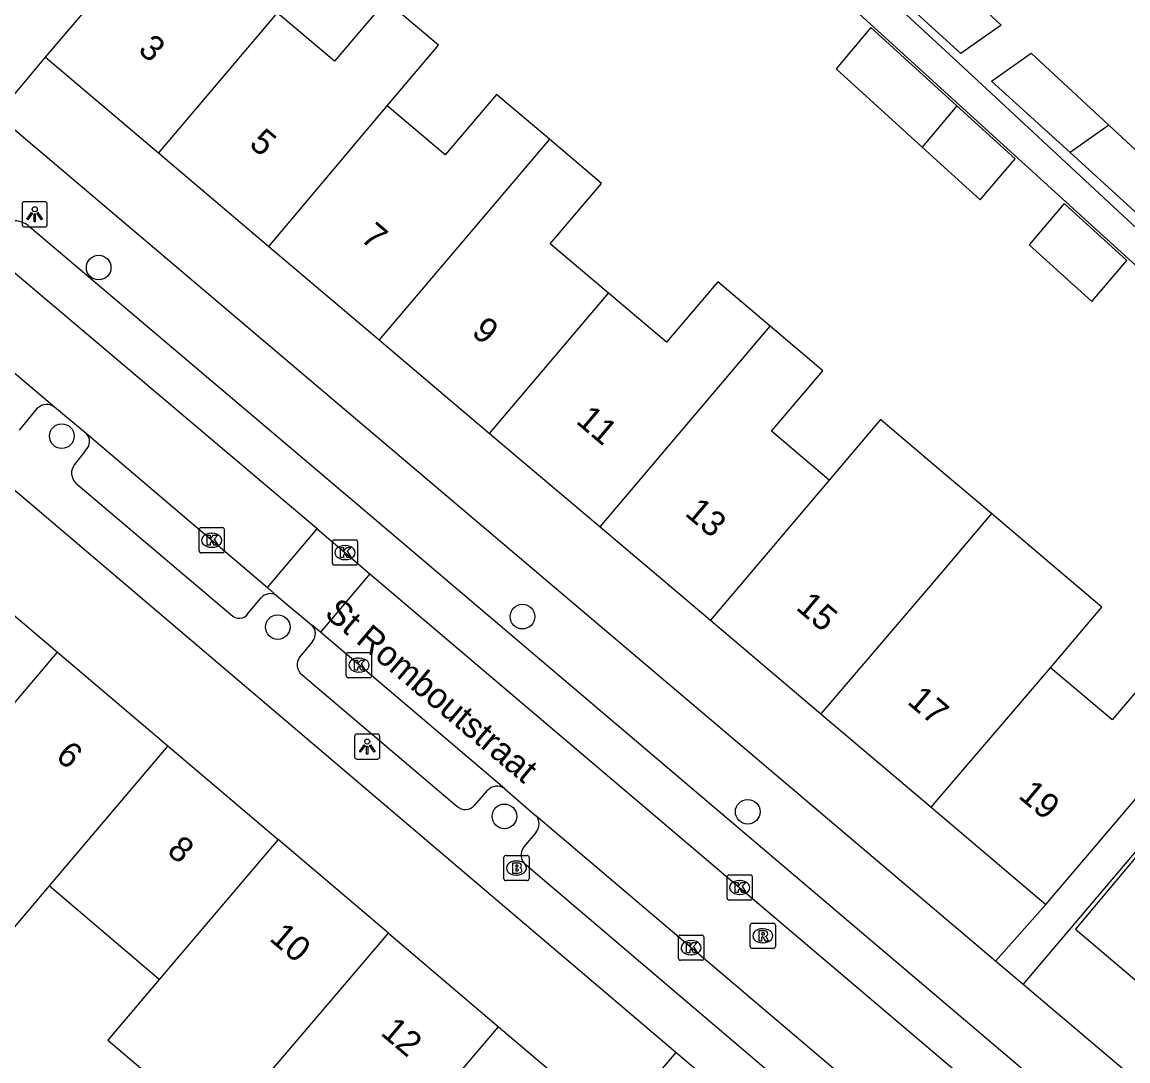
# Model space of a CAD drawing. Extents: x 162532 to 163264, y 381233 to 382042.
# Drawn here: x 162812.29 to 162856.16, y 381629.69 to 381670.92 of the extents above; entities that cross this region are included whole.
import ezdxf

# ---------------------------------------------------------------- set-up
doc = ezdxf.new("R2010")
doc.units = 0
for name, color, linetype in [('IMGEO_Boom', 7, 'Continuous'), ('IMGEO_Brandkraan', 7, 'Continuous'), ('IMGEO_Kolk', 7, 'Continuous'), ('IMGEO_Lichtpunt', 7, 'Continuous'), ('IMGEO_Openbare_ruimte_label', 7, 'Continuous'), ('IMGEO_Pand', 7, 'Continuous'), ('IMGEO_Pand_nummerreeks', 7, 'Continuous'), ('IMGEO_Rijbaan_lokaal_open', 7, 'Continuous'), ('IMGEO_Rioolput', 7, 'Continuous'), ('IMGEO_Voetpad_open', 7, 'Continuous')]:
    doc.layers.add(name, color=color, linetype=linetype)

msp = doc.modelspace()

# ---------------------------------------------------------------- linework, layer by layer
at = {"layer": 'IMGEO_Boom'}
for centre in [(162815.332, 381661.173), (162813.869, 381654.484), (162832.145, 381647.32), (162822.437, 381646.905), (162831.429, 381639.392), (162841.082, 381639.575)]:
    msp.add_circle(centre, 0.489, dxfattribs=at)
at = {"layer": 'IMGEO_Brandkraan'}
for p, q in [((162831.406, 381636.915), (162831.406, 381637.767)), ((162831.481, 381637.841), (162832.333, 381637.841)), ((162831.894, 381637.621), (162831.919, 381637.621)), ((162832.407, 381637.767), (162832.407, 381636.915)), ((162832.333, 381636.841), (162831.481, 381636.841)), ((162831.917, 381637.061), (162831.892, 381637.061))]:
    msp.add_line(p, q, dxfattribs=at)
for points in [[(162831.406, 381636.915), (162831.406, 381637.767)], [(162831.481, 381637.841), (162832.333, 381637.841)], [(162832.407, 381637.767), (162832.407, 381636.915)], [(162831.754, 381637.541), (162831.754, 381637.141), (162831.967, 381637.141)], [(162831.985, 381637.541), (162831.754, 381637.541)], [(162831.933, 381637.46), (162831.879, 381637.46), (162831.879, 381637.384)], [(162831.879, 381637.384), (162831.932, 381637.384)], [(162831.941, 381637.308), (162831.879, 381637.308), (162831.879, 381637.227)], [(162831.879, 381637.227), (162831.941, 381637.227)], [(162832.333, 381636.841), (162831.481, 381636.841)]]:
    msp.add_lwpolyline(points, dxfattribs=at)
for centre, radius, start, end in [((162831.483, 381637.765), 0.0765, 91.552, 178.448), ((162831.483, 381637.765), 0.0765, 91.552, 178.448), ((162832.331, 381637.765), 0.0765, 1.552, 88.448), ((162832.331, 381637.765), 0.0765, 1.552, 88.448), ((162831.934, 381637.422), 0.0379, 267.8285, 90.9355), ((162831.942, 381637.267), 0.0404, 269.8759, 90.5077), ((162831.989, 381637.396), 0.145, 59.4692, 91.5367), ((162832.014, 381637.443), 0.0922, 285.5137, 58.1501), ((162832.019, 381637.251), 0.105, 301.3115, 78.989), ((162831.483, 381636.917), 0.0765, 181.552, 268.448), ((162831.483, 381636.917), 0.0765, 181.552, 268.448), ((162831.973, 381637.392), 0.251, 268.6676, 293.5347), ((162832.331, 381636.917), 0.0765, 271.552, 358.448), ((162832.331, 381636.917), 0.0765, 271.552, 358.448)]:
    msp.add_arc(centre, radius, start, end, dxfattribs=at)
for centre, major_axis, ratio, start_param, end_param in [((162831.893, 381637.341), (-0.387, 0.002), 0.722429, 4.712389, 7.853982), ((162831.918, 381637.341), (-0.39, 0.002), 0.717154, 1.570796, 4.712389)]:
    msp.add_ellipse(centre, major_axis=major_axis, ratio=ratio, start_param=start_param, end_param=end_param, dxfattribs=at)
at = {"layer": 'IMGEO_Kolk'}
for p, q in [((162819.316, 381649.925), (162819.316, 381650.777)), ((162819.391, 381650.851), (162820.243, 381650.851)), ((162820.317, 381650.777), (162820.317, 381649.925)), ((162819.804, 381650.631), (162819.829, 381650.631)), ((162824.68, 381650.363), (162825.532, 381650.363)), ((162819.827, 381650.071), (162819.802, 381650.071)), ((162824.605, 381649.437), (162824.605, 381650.289)), ((162825.093, 381650.143), (162825.118, 381650.143)), ((162825.606, 381650.289), (162825.606, 381649.437)), ((162820.243, 381649.851), (162819.391, 381649.851)), ((162825.116, 381649.583), (162825.091, 381649.583)), ((162825.532, 381649.363), (162824.68, 381649.363)), ((162825.157, 381644.969), (162825.157, 381645.821)), ((162825.232, 381645.895), (162826.084, 381645.895)), ((162825.645, 381645.675), (162825.67, 381645.675)), ((162826.158, 381645.821), (162826.158, 381644.969)), ((162825.668, 381645.115), (162825.643, 381645.115)), ((162826.084, 381644.895), (162825.232, 381644.895)), ((162840.263, 381636.143), (162840.263, 381636.995)), ((162840.338, 381637.069), (162841.19, 381637.069)), ((162840.751, 381636.849), (162840.776, 381636.849)), ((162841.264, 381636.995), (162841.264, 381636.143)), ((162841.19, 381636.069), (162840.338, 381636.069)), ((162840.774, 381636.289), (162840.749, 381636.289)), ((162838.335, 381633.755), (162838.335, 381634.607)), ((162838.41, 381634.681), (162839.262, 381634.681)), ((162839.336, 381634.607), (162839.336, 381633.755)), ((162838.823, 381634.461), (162838.848, 381634.461)), ((162839.262, 381633.681), (162838.41, 381633.681)), ((162838.846, 381633.901), (162838.821, 381633.901))]:
    msp.add_line(p, q, dxfattribs=at)
for points in [[(162819.316, 381649.925), (162819.316, 381650.777)], [(162819.391, 381650.851), (162820.243, 381650.851)], [(162820.317, 381650.777), (162820.317, 381649.925)], [(162819.637, 381650.551), (162819.76, 381650.551), (162819.76, 381650.4), (162819.89, 381650.551), (162820.054, 381650.551), (162819.908, 381650.4), (162820.061, 381650.151), (162819.909, 381650.151), (162819.824, 381650.315), (162819.76, 381650.248), (162819.76, 381650.151), (162819.637, 381650.151), (162819.637, 381650.551)], [(162824.68, 381650.363), (162825.532, 381650.363)], [(162824.605, 381649.437), (162824.605, 381650.289)], [(162824.926, 381650.063), (162825.049, 381650.063), (162825.049, 381649.912), (162825.179, 381650.063), (162825.343, 381650.063), (162825.197, 381649.912), (162825.35, 381649.663), (162825.198, 381649.663), (162825.113, 381649.827), (162825.049, 381649.76), (162825.049, 381649.663), (162824.926, 381649.663), (162824.926, 381650.063)], [(162825.606, 381650.289), (162825.606, 381649.437)], [(162820.243, 381649.851), (162819.391, 381649.851)], [(162825.532, 381649.363), (162824.68, 381649.363)], [(162825.157, 381644.969), (162825.157, 381645.821)], [(162825.232, 381645.895), (162826.084, 381645.895)], [(162825.478, 381645.595), (162825.601, 381645.595), (162825.601, 381645.444), (162825.731, 381645.595), (162825.895, 381645.595), (162825.749, 381645.444), (162825.902, 381645.195), (162825.75, 381645.195), (162825.665, 381645.359), (162825.601, 381645.292), (162825.601, 381645.195), (162825.478, 381645.195), (162825.478, 381645.595)], [(162826.158, 381645.821), (162826.158, 381644.969)], [(162826.084, 381644.895), (162825.232, 381644.895)], [(162840.263, 381636.143), (162840.263, 381636.995)], [(162840.338, 381637.069), (162841.19, 381637.069)], [(162840.584, 381636.769), (162840.707, 381636.769), (162840.707, 381636.618), (162840.837, 381636.769), (162841.001, 381636.769), (162840.855, 381636.618), (162841.008, 381636.369), (162840.856, 381636.369), (162840.771, 381636.533), (162840.707, 381636.466), (162840.707, 381636.369), (162840.584, 381636.369), (162840.584, 381636.769)], [(162841.264, 381636.995), (162841.264, 381636.143)], [(162841.19, 381636.069), (162840.338, 381636.069)], [(162838.335, 381633.755), (162838.335, 381634.607)], [(162838.41, 381634.681), (162839.262, 381634.681)], [(162839.336, 381634.607), (162839.336, 381633.755)], [(162838.656, 381634.381), (162838.779, 381634.381), (162838.779, 381634.23), (162838.909, 381634.381), (162839.073, 381634.381), (162838.927, 381634.23), (162839.08, 381633.981), (162838.928, 381633.981), (162838.843, 381634.145), (162838.779, 381634.078), (162838.779, 381633.981), (162838.656, 381633.981), (162838.656, 381634.381)], [(162839.262, 381633.681), (162838.41, 381633.681)]]:
    msp.add_lwpolyline(points, dxfattribs=at)
for centre, start, end in [((162819.393, 381650.775), 91.552, 178.448), ((162819.393, 381650.775), 91.552, 178.448), ((162820.241, 381650.775), 1.552, 88.448), ((162820.241, 381650.775), 1.552, 88.448), ((162824.682, 381650.287), 91.552, 178.448), ((162824.682, 381650.287), 91.552, 178.448), ((162825.53, 381650.287), 1.552, 88.448), ((162825.53, 381650.287), 1.552, 88.448), ((162819.393, 381649.927), 181.552, 268.448), ((162819.393, 381649.927), 181.552, 268.448), ((162820.241, 381649.927), 271.552, 358.448), ((162820.241, 381649.927), 271.552, 358.448), ((162824.682, 381649.439), 181.552, 268.448), ((162824.682, 381649.439), 181.552, 268.448), ((162825.53, 381649.439), 271.552, 358.448), ((162825.53, 381649.439), 271.552, 358.448), ((162825.234, 381645.819), 91.552, 178.448), ((162825.234, 381645.819), 91.552, 178.448), ((162826.082, 381645.819), 1.552, 88.448), ((162826.082, 381645.819), 1.552, 88.448), ((162825.234, 381644.971), 181.552, 268.448), ((162825.234, 381644.971), 181.552, 268.448), ((162826.082, 381644.971), 271.552, 358.448), ((162826.082, 381644.971), 271.552, 358.448), ((162840.34, 381636.993), 91.552, 178.448), ((162840.34, 381636.993), 91.552, 178.448), ((162841.188, 381636.993), 1.552, 88.448), ((162841.188, 381636.993), 1.552, 88.448), ((162840.34, 381636.145), 181.552, 268.448), ((162840.34, 381636.145), 181.552, 268.448), ((162841.188, 381636.145), 271.552, 358.448), ((162841.188, 381636.145), 271.552, 358.448), ((162838.412, 381634.605), 91.552, 178.448), ((162838.412, 381634.605), 91.552, 178.448), ((162839.26, 381634.605), 1.552, 88.448), ((162839.26, 381634.605), 1.552, 88.448), ((162838.412, 381633.757), 181.552, 268.448), ((162838.412, 381633.757), 181.552, 268.448), ((162839.26, 381633.757), 271.552, 358.448), ((162839.26, 381633.757), 271.552, 358.448)]:
    msp.add_arc(centre, 0.0765, start, end, dxfattribs=at)
for centre, major_axis, ratio, start_param, end_param in [((162819.803, 381650.351), (-0.387, 0.002), 0.722429, 4.712389, 7.853982), ((162819.828, 381650.351), (-0.39, 0.002), 0.717154, 1.570796, 4.712389), ((162825.092, 381649.863), (-0.387, 0.002), 0.722429, 4.712389, 7.853982), ((162825.117, 381649.863), (-0.39, 0.002), 0.717154, 1.570796, 4.712389), ((162825.644, 381645.395), (-0.387, 0.002), 0.722429, 4.712389, 7.853982), ((162825.669, 381645.395), (-0.39, 0.002), 0.717154, 1.570796, 4.712389), ((162840.75, 381636.569), (-0.387, 0.002), 0.722429, 4.712389, 7.853982), ((162840.775, 381636.569), (-0.39, 0.002), 0.717154, 1.570796, 4.712389), ((162838.822, 381634.181), (-0.387, 0.002), 0.722429, 4.712389, 7.853982), ((162838.847, 381634.181), (-0.39, 0.002), 0.717154, 1.570796, 4.712389)]:
    msp.add_ellipse(centre, major_axis=major_axis, ratio=ratio, start_param=start_param, end_param=end_param, dxfattribs=at)
at = {"layer": 'IMGEO_Lichtpunt'}
for p, q in [((162812.295, 381663.69), (162812.295, 381662.883)), ((162812.295, 381663.69), (162812.295, 381662.883)), ((162813.197, 381663.785), (162812.389, 381663.785)), ((162813.197, 381663.785), (162812.389, 381663.785)), ((162813.291, 381662.883), (162813.291, 381663.69)), ((162813.291, 381662.883), (162813.291, 381663.69)), ((162812.389, 381662.789), (162813.197, 381662.789)), ((162812.389, 381662.789), (162813.197, 381662.789)), ((162825.487, 381642.565), (162825.487, 381641.758)), ((162825.487, 381642.565), (162825.487, 381641.758)), ((162826.389, 381642.66), (162825.581, 381642.66)), ((162826.389, 381642.66), (162825.581, 381642.66)), ((162826.483, 381641.758), (162826.483, 381642.565)), ((162826.483, 381641.758), (162826.483, 381642.565)), ((162825.581, 381641.664), (162826.389, 381641.664)), ((162825.581, 381641.664), (162826.389, 381641.664))]:
    msp.add_line(p, q, dxfattribs=at)
for points in [[(162812.669, 381663.354), (162812.708, 381663.326), (162812.52, 381663.064), (162812.482, 381663.091), (162812.669, 381663.354)], [(162812.771, 381663.306), (162812.818, 381663.306), (162812.818, 381662.984), (162812.771, 381662.984), (162812.771, 381663.306)], [(162812.881, 381663.326), (162812.919, 381663.353), (162813.106, 381663.091), (162813.067, 381663.063), (162812.881, 381663.326)], [(162825.861, 381642.229), (162825.9, 381642.201), (162825.712, 381641.939), (162825.674, 381641.966), (162825.861, 381642.229)], [(162825.963, 381642.181), (162826.01, 381642.181), (162826.01, 381641.859), (162825.963, 381641.859), (162825.963, 381642.181)], [(162826.073, 381642.201), (162826.111, 381642.228), (162826.298, 381641.966), (162826.259, 381641.938), (162826.073, 381642.201)]]:
    msp.add_lwpolyline(points, dxfattribs=at)
for centre in [(162812.794, 381663.488), (162825.986, 381642.363)]:
    msp.add_circle(centre, 0.0994, dxfattribs=at)
for centre, start, end in [((162812.389, 381663.69), 90, 180), ((162812.389, 381663.69), 90, 180), ((162813.197, 381663.69), 0, 90), ((162813.197, 381663.69), 0, 90), ((162812.389, 381662.883), 180, 270), ((162812.389, 381662.883), 180, 270), ((162813.197, 381662.883), 270, 0), ((162813.197, 381662.883), 270, 360), ((162825.581, 381642.565), 90, 180), ((162825.581, 381642.565), 90, 180), ((162826.389, 381642.565), 0, 90), ((162826.389, 381642.565), 0, 90), ((162825.581, 381641.758), 180, 270), ((162825.581, 381641.758), 180, 270), ((162826.389, 381641.758), 270, 0), ((162826.389, 381641.758), 270, 360)]:
    msp.add_arc(centre, 0.0946, start, end, dxfattribs=at)
at = {"layer": 'IMGEO_Pand'}
for points in [[(162846.86, 381674.769), (162851.137, 381670.798), (162849.541, 381669.672), (162845.216, 381673.608)], [(162813.228, 381669.519), (162815.562, 381672.274)], [(162826.776, 381667.595), (162828.812, 381669.998), (162826.729, 381671.763), (162824.693, 381669.36), (162822.416, 381671.289)], [(162822.416, 381671.289), (162817.704, 381665.727)], [(162849.383, 381667.591), (162845.97, 381670.698), (162844.584, 381669.062), (162847.997, 381665.955)], [(162853.868, 381665.734), (162850.749, 381668.572), (162852.331, 381669.689), (162855.414, 381666.826)], [(162813.228, 381669.519), (162817.704, 381665.727)], [(162833.211, 381666.271), (162831.117, 381668.045), (162829.081, 381665.642), (162826.776, 381667.595)], [(162822.083, 381662.016), (162826.776, 381667.595)], [(162849.383, 381667.591), (162847.997, 381665.955)], [(162847.997, 381665.955), (162850.303, 381663.856), (162851.689, 381665.492), (162849.383, 381667.591)], [(162855.414, 381666.826), (162859.622, 381662.919), (162858.404, 381661.606), (162853.868, 381665.734)], [(162855.414, 381666.826), (162853.868, 381665.734)], [(162833.211, 381666.271), (162826.462, 381658.305)], [(162835.554, 381660.157), (162833.247, 381662.112), (162835.283, 381664.515), (162833.211, 381666.271)], [(162817.704, 381665.727), (162822.083, 381662.016)], [(162856.122, 381661.459), (162853.639, 381663.718), (162852.253, 381662.082), (162854.735, 381659.823), (162856.122, 381661.459)], [(162822.083, 381662.016), (162826.462, 381658.305)], [(162841.97, 381658.849), (162839.892, 381660.61), (162837.855, 381658.207), (162835.554, 381660.157)], [(162830.842, 381654.594), (162835.554, 381660.157)], [(162835.221, 381650.884), (162841.97, 381658.849)], [(162844.313, 381652.735), (162842.021, 381654.677), (162844.057, 381657.08), (162841.97, 381658.849)], [(162826.462, 381658.305), (162830.842, 381654.594)], [(162850.749, 381651.41), (162848.666, 381653.175), (162846.349, 381655.138), (162844.313, 381652.735)], [(162830.842, 381654.594), (162835.221, 381650.884)], [(162844.313, 381652.735), (162839.6, 381647.173)], [(162850.749, 381651.41), (162848.713, 381649.007), (162843.98, 381643.462)], [(162853.1, 381645.29), (162855.136, 381647.693), (162853.053, 381649.458), (162850.749, 381651.41)], [(162835.221, 381650.884), (162839.6, 381647.173)], [(162809.322, 381649.618), (162813.697, 381645.903)], [(162839.6, 381647.173), (162843.98, 381643.462)], [(162808.987, 381640.357), (162813.697, 381645.903)], [(162813.697, 381645.903), (162818.073, 381642.188)], [(162859.663, 381643.857), (162857.58, 381645.622), (162855.544, 381643.219), (162853.1, 381645.29)], [(162848.359, 381639.752), (162853.1, 381645.29)], [(162852.914, 381635.892), (162856.147, 381639.707), (162857.627, 381641.454), (162859.663, 381643.857)], [(162843.98, 381643.462), (162848.359, 381639.752)], [(162863.237, 381636.7), (162860.84, 381638.731), (162862.87, 381641.156), (162860.788, 381642.922), (162858.757, 381640.496), (162857.296, 381638.751), (162854.086, 381634.917), (162858.532, 381631.147)], [(162818.073, 381642.188), (162813.366, 381636.633)], [(162818.073, 381642.188), (162822.448, 381638.473)], [(162813.366, 381636.633), (162811.32, 381634.226), (162809.238, 381635.993), (162811.286, 381638.402), (162808.987, 381640.357)], [(162848.359, 381639.752), (162852.914, 381635.892)], [(162822.448, 381638.473), (162817.732, 381632.92)], [(162826.824, 381634.758), (162822.448, 381638.473)], [(162817.732, 381632.92), (162813.366, 381636.633)], [(162820.066, 381626.801), (162826.824, 381634.758)], [(162826.824, 381634.758), (162831.199, 381631.044)], [(162817.732, 381632.92), (162815.691, 381630.516), (162818.218, 381628.37), (162820.066, 381626.801)], [(162826.477, 381625.484), (162831.199, 381631.044)], [(162831.199, 381631.044), (162835.786, 381627.149)]]:
    msp.add_lwpolyline(points, dxfattribs=at)
at = {"layer": 'IMGEO_Rijbaan_lokaal_open'}
for points in [[(162823.995, 381650.801), (162811.413, 381661.436), (162809.303, 381663.293)], [(162805.425, 381662.797), (162807.552, 381660.807), (162809.65, 381658.966), (162813.578, 381655.64)], [(162813.578, 381655.64), (162814.832, 381654.599)], [(162814.832, 381654.599), (162822.027, 381648.47)], [(162822.027, 381648.47), (162823.995, 381650.801)], [(162823.995, 381650.801), (162825.09, 381649.875), (162826.092, 381649.024)], [(162826.092, 381649.024), (162824.128, 381646.697)], [(162826.092, 381649.024), (162869.033, 381612.565)], [(162822.404, 381648.149), (162822.027, 381648.47)], [(162822.404, 381648.149), (162823.781, 381646.991)], [(162824.128, 381646.697), (162823.781, 381646.991)], [(162831.43, 381640.494), (162824.128, 381646.697)], [(162831.43, 381640.494), (162832.662, 381639.429)], [(162850.293, 381624.446), (162832.662, 381639.429)]]:
    msp.add_lwpolyline(points, dxfattribs=at)
at = {"layer": 'IMGEO_Rioolput'}
for p, q in [((162841.179, 381634.226), (162841.179, 381635.078)), ((162841.254, 381635.152), (162842.106, 381635.152)), ((162842.18, 381635.078), (162842.18, 381634.226)), ((162841.667, 381634.932), (162841.692, 381634.932)), ((162842.106, 381634.152), (162841.254, 381634.152)), ((162841.69, 381634.372), (162841.665, 381634.372))]:
    msp.add_line(p, q, dxfattribs=at)
for points in [[(162841.179, 381634.226), (162841.179, 381635.078)], [(162841.254, 381635.152), (162842.106, 381635.152)], [(162842.18, 381635.078), (162842.18, 381634.226)], [(162841.768, 381634.85), (162841.516, 381634.852), (162841.516, 381634.452)], [(162841.516, 381634.452), (162841.64, 381634.452), (162841.64, 381634.614), (162841.651, 381634.614)], [(162841.694, 381634.771), (162841.64, 381634.771), (162841.64, 381634.69)], [(162841.64, 381634.69), (162841.692, 381634.69)], [(162841.698, 381634.585), (162841.769, 381634.452), (162841.909, 381634.452), (162841.844, 381634.578)], [(162842.106, 381634.152), (162841.254, 381634.152)]]:
    msp.add_lwpolyline(points, dxfattribs=at)
for centre, radius, start, end in [((162841.256, 381635.076), 0.0765, 91.552, 178.448), ((162841.256, 381635.076), 0.0765, 91.552, 178.448), ((162842.104, 381635.076), 0.0765, 1.552, 88.448), ((162842.104, 381635.076), 0.0765, 1.552, 88.448), ((162841.65, 381634.561), 0.0533, 26.0293, 88.6989), ((162841.676, 381634.879), 0.19, 274.7715, 282.9687), ((162841.7, 381634.675), 0.0964, 77.0061, 93.1865), ((162841.714, 381634.732), 0.0378, 276.6634, 79.6772), ((162841.767, 381634.74), 0.109, 350.3612, 89.416), ((162841.765, 381634.74), 0.112, 277.5842, 350.9817), ((162841.749, 381634.525), 0.108, 29.5134, 73.7905), ((162841.256, 381634.228), 0.0765, 181.552, 268.448), ((162841.256, 381634.228), 0.0765, 181.552, 268.448), ((162842.104, 381634.228), 0.0765, 271.552, 358.448), ((162842.104, 381634.228), 0.0765, 271.552, 358.448)]:
    msp.add_arc(centre, radius, start, end, dxfattribs=at)
for centre, major_axis, ratio, start_param, end_param in [((162841.666, 381634.652), (-0.387, 0.002), 0.722429, 4.712389, 7.853982), ((162841.691, 381634.652), (-0.39, 0.002), 0.717154, 1.570796, 4.712389)]:
    msp.add_ellipse(centre, major_axis=major_axis, ratio=ratio, start_param=start_param, end_param=end_param, dxfattribs=at)
at = {"layer": 'IMGEO_Voetpad_open'}
for points in [[(162840.567, 381689.245), (162833.97, 381687.029), (162840.83, 381677.561), (162841.654, 381676.737), (162841.55, 381676.625), (162844.979, 381673.441), (162849.256, 381669.47), (162853.533, 381665.498), (162859.126, 381660.304), (162860.659, 381661.956), (162861.989, 381662.547), (162871.296, 381670.433)], [(162817.941, 381675.081), (162826.389, 381685.247), (162829.11, 381686.291), (162832.622, 381682.981), (162866.593, 381652.054), (162866.531, 381651.986)], [(162850.914, 381633.649), (162811.287, 381667.219), (162813.228, 381669.519)], [(162812.522, 381662.862), (162826.436, 381651.063), (162871.782, 381612.563), (162893.937, 381593.76)], [(162838.227, 381630.019), (162807.327, 381656.293)], [(162812.189, 381654.721), (162812.908, 381655.589)], [(162814.805, 381653.918), (162814.376, 381653.355)], [(162814.427, 381652.619), (162820.581, 381647.402)], [(162852.007, 381632.723), (162860.712, 381642.986), (162867.848, 381651.074), (162872.19, 381647.266), (162876.513, 381643.473), (162880.836, 381639.681), (162885.16, 381635.889), (162889.486, 381632.094), (162893.809, 381628.301), (162898.133, 381624.509), (162902.372, 381620.79), (162901.902, 381620.254), (162900.414, 381618.286), (162894.044, 381610.596)], [(162821.269, 381647.455), (162821.768, 381648.047)], [(162823.813, 381646.33), (162823.31, 381645.72)], [(162823.401, 381645.011), (162829.539, 381639.799)], [(162830.249, 381639.841), (162830.764, 381640.416)], [(162832.682, 381638.766), (162832.198, 381638.177)], [(162832.302, 381637.458), (162848.392, 381623.761)], [(162852.914, 381635.892), (162850.914, 381633.649)], [(162852.007, 381632.723), (162850.914, 381633.649)], [(162889.33, 381605.035), (162887.391, 381602.747), (162852.007, 381632.723)], [(162838.227, 381630.019), (162835.786, 381627.149)], [(162839.377, 381629.041), (162838.227, 381630.019)]]:
    msp.add_lwpolyline(points, dxfattribs=at)
for centre, radius, start, end in [((162811.925, 381661.907), 1.126, 58.0111, 96.3941), ((162813.271, 381655.242), 0.502, 52.3761, 136.3297), ((162814.509, 381654.271), 0.461, 310.0441, 45.415), ((162814.805, 381653.015), 0.548, 141.6259, 226.3019), ((162822.139, 381647.767), 0.465, 55.2373, 142.9854), ((162820.905, 381647.688), 0.432, 221.4126, 327.3975), ((162823.453, 381646.644), 0.478, 318.929, 46.6142), ((162823.722, 381645.412), 0.514, 143.2353, 231.3925), ((162831.138, 381640.105), 0.487, 53.1218, 140.2379), ((162829.874, 381640.152), 0.487, 226.4845, 320.2863), ((162832.322, 381639.087), 0.483, 318.3082, 45.1475), ((162832.583, 381637.866), 0.495, 141.0549, 235.406)]:
    msp.add_arc(centre, radius, start, end, dxfattribs=at)

# ---------------------------------------------------------------- texts
at = {"layer": 'IMGEO_Openbare_ruimte_label'}
msp.add_text('St Romboutstraat', height=1, rotation=319.9083, dxfattribs=at).set_placement((162824.243, 381647.369))
at = {"layer": 'IMGEO_Pand_nummerreeks'}
for s, rotation, p in [('3', 319.7245, (162816.852, 381669.751)), ('5', 319.7245, (162821.261, 381666.015)), ('7', 319.7245, (162825.671, 381662.279)), ('9', 319.7245, (162830.08, 381658.542)), ('11', 319.7245, (162834.226, 381655.03)), ('13', 319.7245, (162838.548, 381651.368)), ('15', 319.7268, (162842.958, 381647.631)), ('17', 319.7268, (162847.367, 381643.895)), ('6', 319.6679, (162813.577, 381641.703)), ('19', 319.7245, (162851.777, 381640.159)), ('8', 319.6679, (162817.997, 381637.95)), ('10', 319.6695, (162822.063, 381634.498)), ('12', 319.6679, (162826.475, 381630.752))]:
    msp.add_text(s, height=1, rotation=rotation, dxfattribs=at).set_placement(p)

doc.saveas('drawing.dxf')
